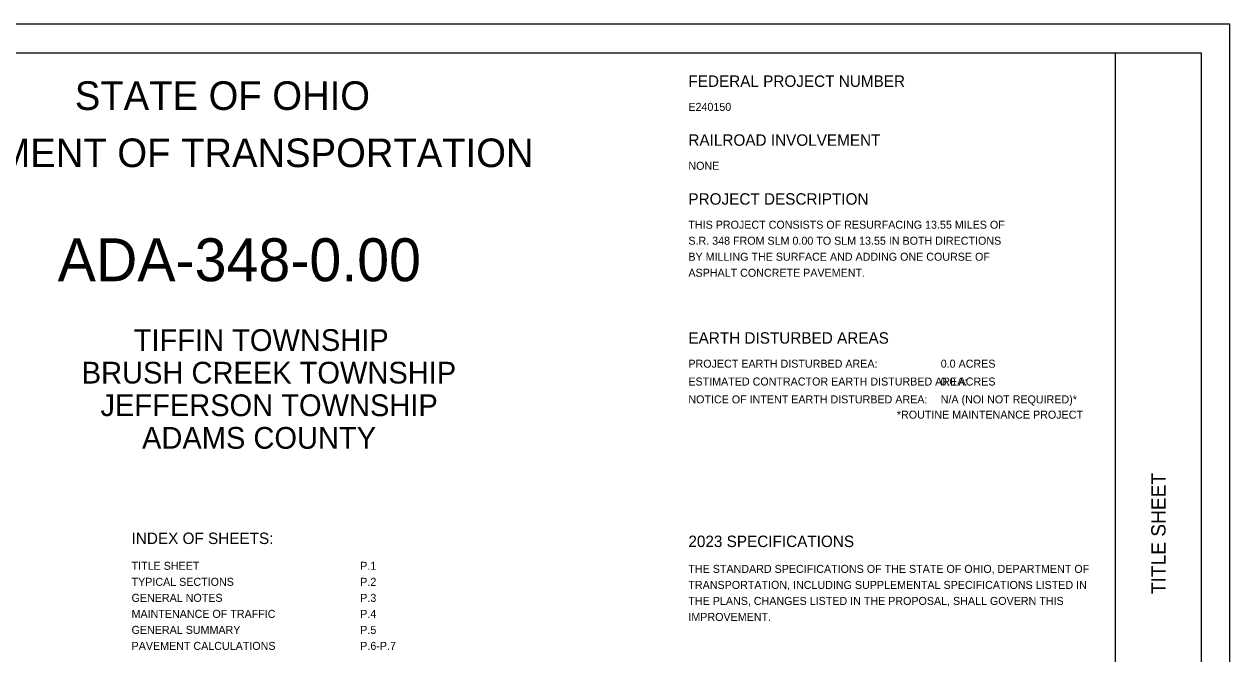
# Model space of a CAD drawing. Extents: x 0 to 34, y 0 to 22.
# Drawn here: x 12.91 to 34, y 10.99 to 22 of the extents above; entities that cross this region are included whole.
import ezdxf

# ---------------------------------------------------------------- set-up
doc = ezdxf.new("R2010")
doc.units = 0
for name, color, linetype in [('SH_Border', 7, 'Continuous'), ('SH_Cut_Line', 7, 'Continuous'), ('SH_Data', 7, 'Continuous'), ('SH_Text', 7, 'Continuous')]:
    doc.layers.add(name, color=color, linetype=linetype)

msp = doc.modelspace()

# ---------------------------------------------------------------- linework, layer by layer
at = {"layer": 'SH_Border'}
msp.add_line((32, 0.5), (32, 21.5), dxfattribs=at)
msp.add_lwpolyline([(1.5, 21.5), (33.5, 21.5), (33.5, 0.5), (1.5, 0.5)], close=True, dxfattribs=at)
at = {"layer": 'SH_Cut_Line'}
msp.add_lwpolyline([(0, 0), (34, 0), (34, 22), (0, 22)], close=True, dxfattribs=at)

# ---------------------------------------------------------------- texts
at = {"layer": 'SH_Data'}
msp.add_text('TITLE SHEET', height=0.25, rotation=90, dxfattribs=at).set_placement((32.875, 12.035))
at = {"layer": 'SH_Text'}
for s, height, p in [('FEDERAL PROJECT NUMBER', 0.2, (24.528, 20.903)), ('STATE OF OHIO', 0.5, (13.795, 20.5)), ('E240150', 0.14, (24.528, 20.483)), ('RAILROAD INVOLVEMENT', 0.2, (24.528, 19.873)), ('DEPARTMENT OF TRANSPORTATION', 0.5, (9.747, 19.5)), ('NONE', 0.14, (24.528, 19.453)), ('PROJECT DESCRIPTION', 0.2, (24.528, 18.843)), ('THIS PROJECT CONSISTS OF RESURFACING 13.55 MILES OF', 0.14, (24.528, 18.423)), ('ADA-348-0.00', 0.75, (13.495, 17.505)), ('S.R. 348 FROM SLM 0.00 TO SLM 13.55 IN BOTH DIRECTIONS', 0.14, (24.528, 18.143)), ('BY MILLING THE SURFACE AND ADDING ONE COURSE OF', 0.14, (24.528, 17.863)), ('ASPHALT CONCRETE PAVEMENT.', 0.14, (24.528, 17.583)), ('TIFFIN TOWNSHIP', 0.38, (14.825, 16.286)), ('EARTH DISTURBED AREAS', 0.2, (24.528, 16.413)), ('BRUSH CREEK TOWNSHIP', 0.38, (13.916, 15.716)), ('PROJECT EARTH DISTURBED AREA:', 0.14, (24.528, 15.993)), ('0.0 ACRES', 0.14, (28.942, 15.993)), ('ESTIMATED CONTRACTOR EARTH DISTURBED AREA:', 0.14, (24.528, 15.681)), ('0.0 ACRES', 0.14, (28.942, 15.681)), ('JEFFERSON TOWNSHIP', 0.38, (14.244, 15.146)), ('NOTICE OF INTENT EARTH DISTURBED AREA:', 0.14, (24.528, 15.369)), ('N/A (NOI NOT REQUIRED)*', 0.14, (28.942, 15.369)), ('*ROUTINE MAINTENANCE PROJECT', 0.14, (28.175, 15.102)), ('ADAMS COUNTY', 0.38, (14.971, 14.576)), ('INDEX OF SHEETS:', 0.2, (14.788, 12.91)), ('2023 SPECIFICATIONS', 0.2, (24.528, 12.857)), ('TITLE SHEET', 0.14, (14.788, 12.459)), ('P.1', 0.14, (18.788, 12.459)), ('THE STANDARD SPECIFICATIONS OF THE STATE OF OHIO, DEPARTMENT OF', 0.14, (24.528, 12.405)), ('TYPICAL SECTIONS', 0.14, (14.788, 12.179)), ('P.2', 0.14, (18.788, 12.179)), ('TRANSPORTATION, INCLUDING SUPPLEMENTAL SPECIFICATIONS LISTED IN', 0.14, (24.528, 12.125)), ('GENERAL NOTES', 0.14, (14.788, 11.899)), ('P.3', 0.14, (18.788, 11.899)), ('THE PLANS, CHANGES LISTED IN THE PROPOSAL, SHALL GOVERN THIS ', 0.14, (24.528, 11.845)), ('MAINTENANCE OF TRAFFIC', 0.14, (14.788, 11.619)), ('P.4', 0.14, (18.788, 11.619)), ('IMPROVEMENT.', 0.14, (24.528, 11.565)), ('GENERAL SUMMARY', 0.14, (14.788, 11.339)), ('P.5', 0.14, (18.788, 11.339)), ('PAVEMENT CALCULATIONS', 0.14, (14.788, 11.059)), ('P.6-P.7', 0.14, (18.788, 11.059))]:
    msp.add_text(s, height=height, dxfattribs=at).set_placement(p)

doc.saveas('drawing.dxf')
